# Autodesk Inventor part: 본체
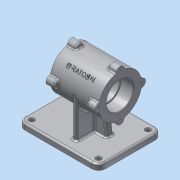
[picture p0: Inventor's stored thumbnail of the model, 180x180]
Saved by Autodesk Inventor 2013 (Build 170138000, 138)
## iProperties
Created: 2015-12
Part Number: 본체
Material: 알루미늄 6061
Document SubType Name: Modeling
Designer: dgall
Density: 2.71 g/cm^3
Mass: 1166.59 g
Surface Area: 817.857 cm^2
Volume: 430.475 cm^3
Author: dgall
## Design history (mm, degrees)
sketch "스케치1"
  geometry: L1 (0, 0)-(85, 0); L2 (0, 23.5)-(22, 23.5); L3 (22, 23.5)-(22, 21); L4 (22, 21)-(63, 21); L5 (63, 21)-(63, 23.5); L6 (63, 23.5)-(85, 23.5); L7 (85, 23.5)-(85, 37); L8 (85, 37)-(0, 37); L9 (0, 37)-(0, 23.5)
  constraints: 18 end point, 5 parallel, 3 perpendicular, 1 horizontal
  dimensions: "d0" = 85 distance of L1.start L1.end; "d1" = 74 diameter of L8 L1; "d3" = 85 distance between parallel lines of L7 L9; "d4" = 0 distance from line of L1.start L9; "d5" = 47 diameter of L2 L1; "d6" = 42 diameter of L4 L1; "d7" = 47 diameter of L6 L1; "d8" = 22 distance of L2.start L2.end; "d9" = 41 distance of L3.end L4.end
revolve "회전1" sketch "스케치1" stored, may be unused: angle "d10" = 90 deg
sketch "스케치2"
  geometry: L1 (-37, 0)-(37, 0); L2 (0, 37)-(0, -37); A1 r 7 centre (-37, 0) between (-36.338, 6.969) and (-36.338, -6.969); A2 r 7 centre (0, 37) between (6.969, 36.338) and (-6.969, 36.338); A3 r 7 centre (37, 0) between (36.338, -6.969) and (36.338, 6.969); A4 r 7 centre (0, -37) between (-6.969, -36.338) and (6.969, -36.338); 1 further point
  constraints: 8 point on circle, 4 centre point, 4 end point, 1 horizontal, 1 perpendicular, 13 other
  dimensions: "d11" = 14 diameter of A4; "d13" = 14 diameter of A1; "d14" = 14 diameter of A2; "d15" = 14 diameter of A3
extrude "돌출1" join sketch "스케치2" distance "d16" = 15; taper "d17" = 0 deg
node "작업 평면1"
fillet "모깎기1" dims "d19" = 0.3
chamfer "모따기1" distance "d20" = 1; stored, may be unused: second distance "d21" = 2, angle "d22" = 45 deg
chamfer "모따기2" distance "d23" = 1; stored, may be unused: second distance "d24" = 2, angle "d25" = 45 deg
sketch "스케치3"
  geometry: A1 r 7 centre (0, 0) between (0.662, 6.969) and (0.662, -6.969) reference; A2 r 7 centre (37, -37) between (30.031, -36.338) and (43.969, -36.338) reference; A3 r 7 centre (74, 0) between (73.338, -6.969) and (73.338, 6.969) reference; A4 r 7 centre (37, 37) between (43.969, 36.338) and (30.031, 36.338) reference
sketch "스케치4"
  geometry: A1 r 7 centre (37, 37) between (43.969, 36.338) and (30.031, 36.338) reference; A2 r 7 centre (0, 0) between (0.662, 6.969) and (0.662, -6.969) reference; A3 r 7 centre (37, -37) between (30.031, -36.338) and (43.969, -36.338) reference; A4 r 7 centre (74, 0) between (73.338, -6.969) and (73.338, 6.969) reference
hole "구멍1" sketch "스케치4" at (74, 0), (37, -37), (0, 0), (37, 37) diameter "d26" = 3.242; stored, may be unused: countersink angle "d30" = 90 deg, drill point angle "d32" = 118 deg; dims "d27" = 9, "d28" = 4, "d29" = 2, "d31" = 11
hole "구멍2" sketch "스케치3" diameter "d33" = 3.242; stored, may be unused: countersink angle "d37" = 90 deg, drill point angle "d39" = 118 deg; dims "d34" = 9, "d35" = 4, "d36" = 2, "d38" = 11
node "작업 평면2"
sketch "스케치5"
  geometry: L1 (15, 37)-(70, 37) reference; L2 (70, 44)-(70, 36.338) reference; L3 (85, 44)-(70, 44) reference; L4 (85, 36.338)-(85, 44) reference; L5 (85, 6.969)-(85, 36.338) reference; L6 (85, -7)-(85, 7) reference; L7 (85, -36.338)-(85, -6.969) reference; L8 (85, -44)-(85, -36.338) reference; L9 (85, -44)-(70, -44) reference; L10 (70, -36.338)-(70, -44) reference; L11 (15, -37)-(70, -37) reference; L12 (15, -36.338)-(15, -44) reference; L13 (15, -44)-(0, -44) reference; L14 (0, -44)-(0, -36.338) reference; L15 (0, -36.338)-(0, -6.969) reference; L16 (0, 6.969)-(0, 36.338) reference; L17 (0, -7)-(0, 7) reference; L18 (0, 36.338)-(0, 44) reference; L19 (15, 44)-(0, 44) reference; L20 (15, 44)-(15, 36.338) reference; L21 (-37.5, 55)-(102.5, 55); L22 (102.5, 55)-(102.5, -55); L23 (102.5, -55)-(-37.5, -55); L24 (-37.5, -55)-(-37.5, 55); L25 (0, 0)-(85, 0); L26 (42.5, -37)-(42.5, 37)
  constraints: 12 end point, 3 midpoint, 2 parallel, 1 horizontal, 1 perpendicular
  dimensions: "d41" = 140 distance of L21.start L21.end; "d43" = 110 distance of L21.end L22.end; "d44" = 55 distance between parallel lines of L25 L21; "d45" = 80 distance between parallel lines of L26 L24
node "작업 평면4"
  node "작업 평면3"
sketch "스케치9"
  geometry: L1 (15, -30.622)-(15, -20.767) reference; L2 (15, -20.767)-(0, -20.767) reference; L3 (0, -20.767)-(0, 20.767) reference; L4 (0, 20.767)-(15, 20.767) reference; L5 (15, 20.767)-(15, 30.622) reference; L6 (15, 30.622)-(0, 30.622) reference; L7 (0, 30.622)-(0, 30.622) reference; L8 (0, 30.622)-(15, 30.622) reference; L9 (15, 30.622)-(15, 20.767) reference; L10 (15, 20.767)-(0, 20.767) reference; L11 (0, 20.767)-(0, -20.767) reference; L12 (0, -20.767)-(15, -20.767) reference; L13 (15, -20.767)-(15, -30.622) reference; L14 (15, -30.622)-(0, -30.622) reference; L15 (0, -30.622)-(0, -30.622) reference; L16 (0, -30.622)-(15, -30.622) reference; L17 (70, -20.767)-(70, -30.622) reference; L18 (70, -30.622)-(85, -30.622) reference; L19 (85, -30.622)-(85, -30.622) reference; L20 (85, -30.622)-(70, -30.622) reference; L21 (70, -30.622)-(70, -20.767) reference; L22 (70, -20.767)-(85, -20.767) reference; L23 (85, 20.767)-(85, -20.767) reference; L24 (85, 20.767)-(70, 20.767) reference; L25 (70, 20.767)-(70, 30.622) reference; L26 (70, 30.622)-(85, 30.622) reference; L27 (85, 30.622)-(85, 30.622) reference; L28 (85, 30.622)-(70, 30.622) reference; L29 (70, 30.622)-(70, 20.767) reference; L30 (70, 20.767)-(85, 20.767) reference; L31 (85, -20.767)-(85, 20.767) reference; L32 (85, -20.767)-(70, -20.767) reference; L33 (0, 37)-(85, 37) reference; L34 (42.5, 37)-(42.5, -2.606); L35 (17.613, 3.602)-(67.387, 3.602); L36 (67.387, 3.602)-(67.387, -3.602); L37 (67.387, -3.602)-(17.613, -3.602); L38 (17.613, -3.602)-(17.613, 3.602); L39 (17.613, 0)-(67.387, 0); L40 (42.5, 3.602)-(42.5, -3.602); 1 further point
  constraints: 6 end point, 5 midpoint, 1 perpendicular, 2 other
  dimensions: "d94" = 0 distance between parallel lines of L34 L40; "d96" = 0 distance from line of point (0, 0) L39
feature "엠보싱1" sketch "스케치9" dims "d0" = 85, "d1" = 74, "d3" = 85, "d4" = 0, "d5" = 47, "d6" = 42, "d7" = 47, "d8" = 22, "d9" = 41, "d97" = 0.5, "d98" = 0
fillet "모깎기7" dims "d100" = 3
fillet "모깎기8" dims "d101" = 3
extrude "돌출5" join sketch "스케치5" distance "d103" = 10; taper "d104" = 0 deg
fillet "모깎기9" dims "d105" = 12
fillet "모깎기10" dims "d106" = 3
sketch "스케치12"
  geometry: C1 r 4 at (-25.5, 43); C2 r 4 at (-25.5, -43); C3 r 4 at (90.5, -43); C4 r 4 at (90.5, 43); A1 r 9 centre (90.5, -43) between (90.5, -52) and (99.5, -43) reference; A2 r 9 centre (90.5, 43) between (99.5, 43) and (90.5, 52) reference; A3 r 9 centre (-25.5, 43) between (-25.5, 52) and (-34.5, 43) reference; A4 r 9 centre (-25.5, -43) between (-34.5, -43) and (-25.5, -52) reference; 1 further point
  constraints: 4 centre point, 4 coincident
  dimensions: "d107" = 8 diameter of C1; "d109" = 8 diameter of C4; "d110" = 8 diameter of C3; "d111" = 8 diameter of C2
extrude "돌출6" cut sketch "스케치12" distance "d112" = 10; taper "d113" = 0 deg
chamfer "모따기7" distance "d114" = 1; stored, may be unused: second distance "d115" = 2, angle "d116" = 45 deg
chamfer "모따기8" distance "d117" = 1; stored, may be unused: second distance "d118" = 2, angle "d119" = 45 deg
chamfer "모따기9" distance "d120" = 1; stored, may be unused: second distance "d121" = 2, angle "d122" = 45 deg
chamfer "모따기10" distance "d123" = 1; stored, may be unused: second distance "d124" = 2, angle "d125" = 45 deg
node "작업 평면7"
  node "작업 평면6"
node "작업 평면9"
sketch "스케치16"
  geometry: L1 (-55, -80)-(-55, -73) reference; L2 (-52, -70)-(-43, -70) reference; L3 (-43, -70)-(43, -70) reference; L4 (48, -70)-(38, -70) reference; L5 (55, -73)-(43, -73) reference; L6 (43, -70)-(43, -73) reference; L7 (43, -70)-(52, -70) reference; L8 (55, -73)-(55, -80) reference; L9 (-37, 0)-(-37, -70); L10 (37, 0.021)-(37.039, -70); L11 (-37, -70)-(37, -70); C1 r 1.621 at (0, -37) reference; C2 r 1.621 at (0, 37) reference; C3 r 1.621 at (-37, 0) reference; C4 r 1.621 at (37, 0) reference; C5 r 24.5 at (0, 0) reference; A1 r 37 centre (0, 0) between (-9.104, 35.863) and (-35.863, 9.104) reference; A2 r 3 centre (38.77, -9.842) between (38.239, -6.889) and (35.862, -9.104) reference; A3 r 37 centre (0, 0) between (9.104, -35.862) and (35.862, -9.104) reference; A4 r 3 centre (9.842, -38.77) between (9.104, -35.862) and (6.889, -38.239) reference; A5 r 7 centre (0, -37) between (-6.889, -38.239) and (6.889, -38.239) reference; A6 r 3 centre (-9.842, -38.77) between (-6.889, -38.239) and (-9.104, -35.862) reference; A7 r 37 centre (0, 0) between (-35.862, -9.104) and (-9.104, -35.862) reference; A8 r 3 centre (-38.77, -9.842) between (-35.862, -9.104) and (-38.239, -6.889) reference; A9 r 7 centre (-37, 0) between (-38.239, 6.889) and (-38.239, -6.889) reference; A10 r 3 centre (-38.77, 9.842) between (-38.239, 6.889) and (-35.862, 9.104) reference; A11 r 37 centre (0, 0) between (-9.104, 35.862) and (-35.862, 9.104) reference; A12 r 3 centre (-9.842, 38.77) between (-9.104, 35.862) and (-6.889, 38.239) reference; A13 r 7 centre (0, 37) between (6.889, 38.239) and (-6.889, 38.239) reference; A14 r 3 centre (9.842, 38.77) between (6.889, 38.239) and (9.104, 35.862) reference; A15 r 37 centre (0, 0) between (35.862, 9.104) and (9.104, 35.862) reference; A16 r 3 centre (38.77, 9.842) between (35.862, 9.104) and (38.239, 6.889) reference; A17 r 7 centre (37, 0) between (38.239, -6.889) and (38.239, 6.889) reference; A18 r 37 centre (0, 0) between (-36.913, 2.543) and (-36.913, -2.543) reference; A19 r 37 centre (0, 0) between (36.913, -2.543) and (36.913, 2.543) reference; A20 r 3 centre (-52, -73) between (-52, -70) and (-55, -73) reference; A21 r 3 centre (52, -73) between (55, -73) and (52, -70) reference; A22 r 37 centre (0, 0) between (-37, 0) and (37, 0.021); 2 further points
  constraints: 6 end point, 4 point on circle, 3 point on line, 1 centre point, 1 perpendicular, 1 tangent
  dimensions: "d134" = 37 distance from line of L9 A1.centre; "d136" = 37 distance from line of L10 point (0, 0)
extrude "돌출8" join sketch "스케치16" stored distance "d137" = 8; taper "d138" = 0 deg
sketch "스케치17"
  geometry: L1 (-38.5, 0.021)-(-38.5, 0) reference; L2 (-38.5, 0)-(-46.5, 0) reference; L3 (-46.5, 0)-(-46.5, 0.021) reference; L4 (-38.5, 0.021)-(-46.5, 0.021) reference; L5 (-85, 9.104)-(-73, 9.104) reference; L6 (-85, 35.863)-(-85, 9.104) reference; L7 (-73, 35.863)-(-85, 35.863) reference; L8 (-67, 36.913)-(-67, 36.913) reference; L9 (-85, 35.863)-(-73, 35.863) reference; L10 (-85, 9.104)-(-85, 35.863) reference; L11 (-73, 9.104)-(-85, 9.104) reference; L12 (-67, -2.543)-(-67, 2.543) reference; L13 (-85, -35.863)-(-73, -9.104) reference; L14 (-85, -35.863)-(-85, -35.863) reference; L15 (-73, -35.863)-(-85, -35.863) reference; L16 (-67, -36.913)-(-67, -36.913) reference; L17 (-85, -35.863)-(-73, -35.863) reference; L18 (-85, -9.104)-(-85, -35.863) reference; L19 (-73, -9.104)-(-85, -9.104) reference; L20 (-67, 2.543)-(-67, -2.543) reference; L21 (0, -9.104)-(-12, -9.104) reference; L22 (0, -9.104)-(0, -35.862) reference; L23 (-12, -35.863)-(0, -35.862) reference; L24 (-18, -36.913)-(-18, -36.913) reference; L25 (0, -35.862)-(-12, -35.863) reference; L26 (0, -35.862)-(0, -9.104) reference; L27 (-12, -9.104)-(0, -9.104) reference; L28 (-18, 2.543)-(-18, -2.543) reference; L29 (0, 35.862)-(-12, 9.104) reference; L30 (0, 35.862)-(0, 35.862) reference; L31 (-12, 35.863)-(0, 35.862) reference; L32 (-18, 36.913)-(-18, 36.913) reference; L33 (0, 35.862)-(-12, 35.863) reference; L34 (0, 35.862)-(0, 9.104) reference; L35 (-12, 9.104)-(0, 9.104) reference; L36 (-18, -2.543)-(-18, 2.543) reference; L37 (-59.979, 27.915)-(-63.455, 27.915) reference; L38 (-63.455, 27.915)-(-63.455, 27.619) reference; L39 (-63.455, 27.619)-(-60.516, 27.619) reference; L40 (-60.516, 27.619)-(-60.516, 26.662) reference; L41 (-60.516, 26.662)-(-63.138, 26.662) reference; L42 (-63.138, 26.662)-(-63.138, 26.349) reference; L43 (-63.138, 26.349)-(-60.516, 26.349) reference; L44 (-60.516, 26.349)-(-60.516, 25.223) reference; L45 (-59.979, 24.869)-(-59.979, 27.915) reference; L46 (-54.264, 27.286)-(-55.501, 27.286) reference; L47 (-55.501, 27.286)-(-55.501, 28.463) reference; L48 (-55.501, 28.463)-(-55.949, 28.463) reference; L49 (-56.047, 28.28)-(-56.047, 24.936) reference; L50 (-56.047, 24.936)-(-55.501, 24.936) reference; L51 (-55.501, 24.936)-(-55.501, 27.004) reference; L52 (-55.501, 27.004)-(-54.264, 27.004) reference; L53 (-54.264, 27.004)-(-54.264, 27.286) reference; L54 (-52.904, 28.317)-(-53.385, 28.317) reference; L55 (-41.914, 23.852)-(-41.914, 27.781) reference; L56 (-41.914, 27.781)-(-40.05, 27.781) reference; L57 (-40.05, 27.781)-(-40.05, 28.106) reference; L58 (-40.05, 28.106)-(-44.332, 28.106) reference; L59 (-44.332, 28.106)-(-44.332, 27.781) reference; L60 (-44.332, 27.781)-(-42.459, 27.781) reference; L61 (-42.459, 27.781)-(-42.459, 23.852) reference; L62 (-42.459, 23.852)-(-41.914, 23.852) reference; L63 (-36.647, 28.106)-(-37.298, 28.106) reference; L64 (-39.577, 23.852)-(-38.999, 23.852) reference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; A1 r 3 centre (-12, -41) between (-15, -41) and (-12, -44) reference; A2 r 3 centre (-73, -41) between (-73, -44) and (-70, -41) reference; A3 r 3 centre (-12, 41) between (-12, 44) and (-15, 41) reference; A4 r 3 centre (-73, 41) between (-70, 41) and (-73, 44) reference; A5 r 3 centre (-99.5, -73) between (-99.5, -70) and (-102.5, -73) reference; 66 further points; 4 other entities
  constraints: 6 end point, 4 point on line, 1 midpoint, 1 perpendicular, 95 other
  dimensions: "d139" = 25 distance from line of L157 L156.end; "d141" = 25 distance from line of L157 L155.start; "d142" = 97 deg angle of L156 L149; "d143" = 97 deg angle of L155 L149
  node "투영된 루프9"
feature "리브3" dims "d144" = 1, "d145" = 12, "d146" = 0, "d147" = 0, "d148" = 1, "d149" = 1
feature "리브4" dims "d150" = 1, "d151" = 12, "d152" = 0, "d153" = 0, "d154" = 1, "d155" = 1
fillet "모깎기11" dims "d156" = 3
fillet "모깎기12" dims "d157" = 3
fillet "모깎기13" dims "d158" = 3
fillet "모깎기14" dims "d159" = 3
node "솔리드1"
mirror "대칭1"
node "투영된 루프3"
node "투영된 루프7"
node "투영된 루프8"
other parameters: "d18" = 42.5, "d57" = 37, "d58" = 37, "d92" = 45 deg, "d93" = 81.5, "d126" = -37.5, "d127" = 76, "d128" = 37, "d132" = 42.5
